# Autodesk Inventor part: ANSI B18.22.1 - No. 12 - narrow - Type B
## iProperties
Comments: To add or edit properties for Autodesk Inventor files, use iProperties.
Created: 2005-01
Part Number: ANSI B18.22.1 - No. 12 - narrow - Type B
Vendor: Autodesk Inc.
Document SubType Name: Modeling
Designer: John Blackburn
Material: Default
Description: Washer B
Standard: ANSI B18.22.1
Alert: To add or edit properties for Autodesk Inventor files, use iProperties.
Control State: 0
Master: False
Checked Out: False
Shininess: 64.0
Length Units: 11272
Angle Units: 11279
Time Units: 11290
Mass Units: 11286
Length Display Precision: 3
Angle Display Precision: 2
Compacted: True
Classification: un/spsc 31161807
Density: 0.0
Volumn: 0.0
Area: 0.0
PropertySet Name: Model Information
Author: John Blackburn
Revision Number: 8
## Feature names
1. Body [Extrusion]
